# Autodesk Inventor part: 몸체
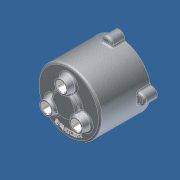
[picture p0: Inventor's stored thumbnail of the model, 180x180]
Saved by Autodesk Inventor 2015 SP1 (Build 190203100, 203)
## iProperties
Created: 2012-05
Part Number: 몸체
Document SubType Name: 모델링
Designer: SeoGD™
Material: 알루미늄 6061
Appearance: 알루미늄 - 평지
Mass: 473.798 g
Surface Area: 687.661 cm^2
Volume: 175.481 cm^3
Density: 2.7 g/cm^3
변환 표준: STEP AP214IS
파일 이름: C:\Users\SeoGD\Desktop\?쒗뿕\紐몄껜.stp
전처리기: Build: 253, Release: 2010 SP1 - Date: Wed 07/29/2009
전송 단위: 밀리미터
불확실성: 0.01
Author: SeoGD™
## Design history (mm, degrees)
sketch "스케치2"
  geometry: C1 r 50 at (0, 0); 1 further point
  constraints: 1 centre point, 1 coincident
  dimensions: "d9" = 100 diameter of C1
extrude "돌출2" new body sketch "스케치2" distance "d10" = 80; taper "d11" = 0 deg
feature "쉘1" dims "d12" = 5
sketch "스케치3" dims "d13" = 55
  geometry: C1 r 7.5 at (0, 27.5); C2 r 12.5 at (0, 27.5); 2 further points
  constraints: 2 centre point, 2 coincident, 2 vertical alignment, 2 other
  dimensions: "d14" = 15 diameter of C1; "d15" = 25 diameter of C2
extrude "돌출3" join sketch "스케치3" distance "d16" = 12; taper "d17" = -10 deg
hole "구멍2" diameter "d20" = 15; stored, may be unused: countersink angle "d24" = 90 deg, drill point angle "d26" = 118 deg; dims "d18" = 10, "d19" = 10, "d21" = 6, "d22" = 4, "d23" = 2, "d25" = 15
chamfer "모따기1" distance "d27" = 1; stored, may be unused: second distance "d28" = 2, angle "d29" = 45 deg
sketch "스케치4"
  geometry: L1 (0, 0)-(0, 88); L2 (0, 70)-(13.16, 70); L3 (-45, 75)-(45, 75) reference; L4 (-50, 80)-(50, 80) reference; L5 (13.16, 70)-(14.5, 75); L6 (20, 80)-(20, 88); L7 (20, 88)-(0, 88); L8 (20, 80)-(14.5, 75)
  constraints: 12 end point, 3 point on line, 2 perpendicular, 1 vertical
  dimensions: "d34" = 40 diameter of L6 L1; "d35" = 105 deg angle of L5 L3; "d36" = 5 distance between parallel lines of L2 L3; "d37" = 8 distance between parallel lines of L7 L4; "d51" = 29 diameter of L5.end L1
revolve "회전1" sketch "스케치4" stored, may be unused: angle "d38" = 90 deg
hole "구멍3" diameter "d41" = 15; stored, may be unused: countersink angle "d45" = 90 deg, drill point angle "d47" = 0 deg; dims "d39" = 10, "d40" = 10, "d42" = 6, "d43" = 22, "d44" = 13, "d46" = 15
chamfer "모따기2" distance "d48" = 1; stored, may be unused: second distance "d49" = 2, angle "d50" = 45 deg
fillet "모깎기1" dims "d52" = 3
fillet "모깎기2" dims "d53" = 3, "d72" = 0.2
sketch "스케치5"
  geometry: A1 r 50 centre (0, 0) between (50, 0) and (-8.074, 49.344) reference; A2 r 8.5 centre (0, 52) between (8.074, 49.344) and (-8.074, 49.344); 1 further point
  constraints: 5 point on circle, 1 centre point, 1 horizontal alignment
  dimensions: "d54" = 90 deg dimension on point (0, 0) A2.centre A1.start; "d55" = 52 distance of A2.centre point (0, 0); "d56" = 17 diameter of A2
extrude "돌출4" join sketch "스케치5" distance "d57" = 20; taper "d58" = 0 deg
fillet "모깎기3" dims "d59" = 3
hole "구멍4" diameter "d62" = 4.134; stored, may be unused: countersink angle "d66" = 90 deg, drill point angle "d68" = 118 deg; dims "d60" = 10, "d61" = 10, "d63" = 12, "d64" = 22, "d65" = 13, "d67" = 15
sketch "스케치6"
  geometry: C1 r 47 at (0, 0) reference; C2 r 42.5 at (0, 0); 1 further point
  constraints: 1 centre point, 1 coincident, 1 other
  dimensions: "d73" = 85 diameter of C2
feature "엠보싱1" sketch "스케치6" dims "d74" = 1, "d75" = 0
node "솔리드1"
node "솔리드 본체"
node "곡면 본체"
pattern_circular "원형 패턴1" dims "d31" = 360 deg
pattern_circular "원형 패턴2" dims "d70" = 360 deg
node "솔리드2"
